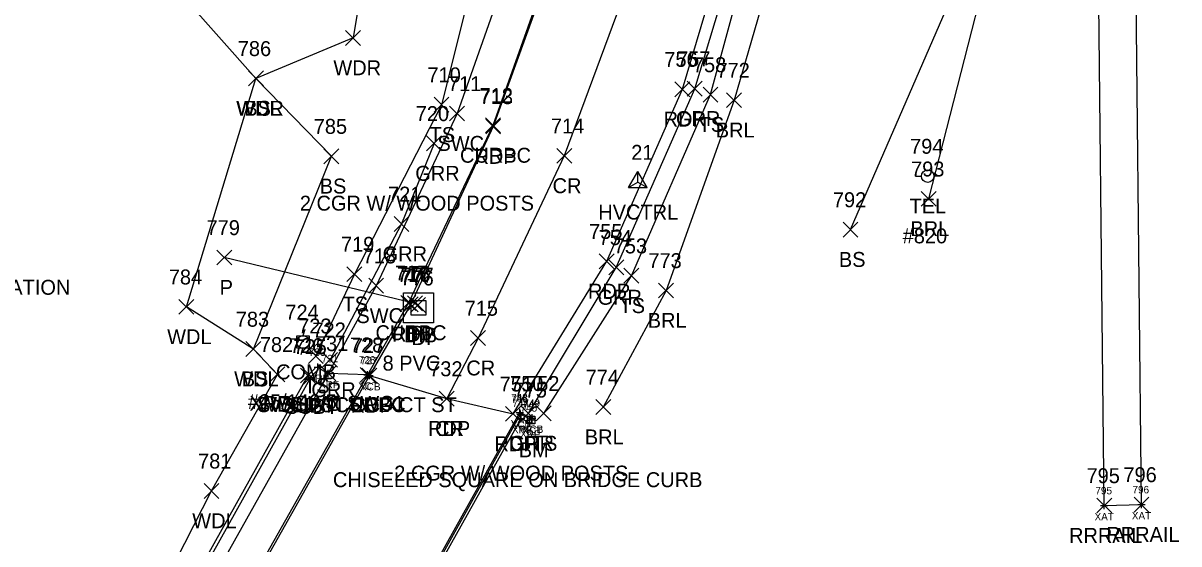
# Model space of a CAD drawing. Extents: x 1764889 to 1767296, y 695936 to 698960.
# Drawn here: x 1766265.6 to 1766420.4, y 696326.9 to 696396.7 of the extents above; entities that cross this region are included whole.
import ezdxf

# ---------------------------------------------------------------- set-up
doc = ezdxf.new("R2010")
doc.units = 0
for name, color, linetype in [('B_A', 7, 'Continuous'), ('B_I', 7, 'Continuous'), ('B_TIC', 7, 'Continuous'), ('BDC', 7, 'Continuous'), ('BR', 7, 'Continuous'), ('BSUBM', 7, 'Continuous'), ('C_A', 7, 'Continuous'), ('C_C', 7, 'Continuous'), ('C_I', 7, 'Continuous'), ('CPBM', 7, 'Continuous'), ('CPSM', 7, 'Continuous'), ('D_A', 7, 'Continuous'), ('D_C', 7, 'Continuous'), ('D_I', 7, 'Continuous'), ('D_TIC', 7, 'Continuous'), ('DCP', 7, 'Continuous'), ('DS', 7, 'Continuous'), ('L_A', 7, 'Continuous'), ('L_I', 7, 'Continuous'), ('L_TIC', 7, 'Continuous'), ('LABL', 7, 'Continuous'), ('LAWA', 7, 'Continuous'), ('LELB', 7, 'Continuous'), ('P_A', 7, 'Continuous'), ('P_I', 7, 'Continuous'), ('P_TIC', 7, 'Continuous'), ('PET', 7, 'Continuous'), ('PRC', 7, 'Continuous'), ('R_A', 7, 'Continuous'), ('R_C', 7, 'Continuous'), ('R_I', 7, 'Continuous'), ('R_TIC', 7, 'Continuous'), ('RC', 7, 'Continuous'), ('RGR', 7, 'Continuous'), ('RR', 7, 'Continuous'), ('RSW', 7, 'Continuous'), ('U_A', 7, 'Continuous'), ('U_C', 7, 'Continuous'), ('U_I', 7, 'Continuous'), ('U_TIC', 7, 'Continuous'), ('UP', 7, 'Continuous'), ('UT', 7, 'Continuous')]:
    doc.layers.add(name, color=color, linetype=linetype)

msp = doc.modelspace()

# ---------------------------------------------------------------- linework, layer by layer
at = {"layer": 'B_TIC'}
for p, q in [((1766305.11, 696350.62), (1766305.18, 696350.62)), ((1766306.5, 696349.77), (1766306.57, 696349.77)), ((1766311.76, 696349.59), (1766311.83, 696349.59)), ((1766312, 696349.5), (1766312.08, 696349.5)), ((1766332.16, 696344.53), (1766332.23, 696344.53)), ((1766332.25, 696344.32), (1766332.32, 696344.32)), ((1766332.33, 696343.76), (1766332.4, 696343.76)), ((1766333.42, 696343.16), (1766333.5, 696343.16)), ((1766333.75, 696343.56), (1766333.82, 696343.56)), ((1766333.81, 696343.8), (1766333.88, 696343.8)), ((1766410.41, 696332.08), (1766410.48, 696332.08)), ((1766415.4, 696332.21), (1766415.47, 696332.21))]:
    msp.add_line(p, q, dxfattribs=at)
for points in [[(1766304.61, 696350.62), (1766305.61, 696350.62)], [(1766305.11, 696350.12), (1766305.11, 696351.12)], [(1766305.99, 696349.77), (1766306.99, 696349.77)], [(1766306.49, 696349.27), (1766306.49, 696350.27)], [(1766311.25, 696349.59), (1766312.25, 696349.59)], [(1766311.5, 696349.5), (1766312.5, 696349.5)], [(1766311.75, 696349.09), (1766311.75, 696350.09)], [(1766312, 696349), (1766312, 696350)], [(1766331.65, 696344.53), (1766332.65, 696344.53)], [(1766331.74, 696344.32), (1766332.74, 696344.32)], [(1766332.15, 696344.03), (1766332.15, 696345.03)], [(1766332.24, 696343.82), (1766332.24, 696344.82)], [(1766332.32, 696343.26), (1766332.32, 696344.26)], [(1766333.8, 696343.3), (1766333.8, 696344.3)], [(1766331.82, 696343.76), (1766332.82, 696343.76)], [(1766332.92, 696343.16), (1766333.92, 696343.16)], [(1766333.24, 696343.56), (1766334.24, 696343.56)], [(1766333.3, 696343.8), (1766334.3, 696343.8)], [(1766333.42, 696342.66), (1766333.42, 696343.66)], [(1766333.74, 696343.06), (1766333.74, 696344.06)], [(1766409.91, 696332.08), (1766410.91, 696332.08)], [(1766410.41, 696331.58), (1766410.41, 696332.58)], [(1766414.9, 696332.21), (1766415.9, 696332.21)], [(1766415.4, 696331.71), (1766415.4, 696332.71)]]:
    msp.add_lwpolyline(points, dxfattribs=at)
at = {"layer": 'BDC'}
for points in [[(1766311.75, 696349.59), (1766247.58, 696235.94)], [(1766312, 696349.5), (1766247.9, 696235.86)], [(1766268.89, 696231.13), (1766332.15, 696344.53), (1766333.8, 696343.8)], [(1766269.14, 696230.99), (1766332.24, 696344.32), (1766333.74, 696343.56)]]:
    msp.add_lwpolyline(points, dxfattribs=at)
at = {"layer": 'BR'}
for points in [[(1766305.11, 696350.62), (1766306.49, 696349.77), (1766243.27, 696237.04), (1766242.22, 696237.68)], [(1766270.49, 696230.33), (1766269.37, 696231.11), (1766332.32, 696343.76), (1766333.42, 696343.16)]]:
    msp.add_lwpolyline(points, dxfattribs=at)
at = {"layer": 'BSUBM'}
msp.add_lwpolyline([(1766410.41, 696332.08), (1766415.4, 696332.21)], dxfattribs=at)
at = {"layer": 'CPBM'}
for p, q in [((1766333.17, 696343.04), (1766333.17, 696344.04)), ((1766333.17, 696344.04), (1766334.17, 696344.04)), ((1766334.17, 696343.04), (1766333.17, 696343.04)), ((1766333.67, 696343.54), (1766333.67, 696343.54)), ((1766333.67, 696343.54), (1766333.67, 696343.54)), ((1766334.17, 696344.04), (1766334.17, 696343.04))]:
    msp.add_line(p, q, dxfattribs=at)
at = {"layer": 'CPSM'}
for p, q in [((1766346.71, 696374.68), (1766347.96, 696376.84)), ((1766349.21, 696374.68), (1766347.96, 696376.84)), ((1766347.96, 696375.4), (1766347.96, 696376.84)), ((1766346.71, 696374.68), (1766347.96, 696375.4)), ((1766347.96, 696375.4), (1766347.96, 696375.4)), ((1766347.96, 696375.4), (1766349.21, 696374.68)), ((1766346.71, 696374.68), (1766349.21, 696374.68))]:
    msp.add_line(p, q, dxfattribs=at)
at = {"layer": 'D_TIC'}
for points in [[(1766291.56, 696364.31), (1766293.56, 696366.31)], [(1766293.56, 696364.31), (1766291.56, 696366.31)], [(1766317.1, 696358.16), (1766319.1, 696360.16)], [(1766319.1, 696358.16), (1766317.1, 696360.16)], [(1766317.51, 696357.93), (1766319.51, 696359.93)], [(1766319.51, 696357.93), (1766317.51, 696359.93)]]:
    msp.add_lwpolyline(points, dxfattribs=at)
at = {"layer": 'DCP'}
msp.add_lwpolyline([(1766318.1, 696359.16), (1766292.56, 696365.31)], dxfattribs=at)
at = {"layer": 'DS'}
for p, q in [((1766316.57, 696360.57), (1766320.57, 696360.57)), ((1766316.57, 696356.57), (1766316.57, 696360.57)), ((1766320.57, 696360.57), (1766320.57, 696356.57)), ((1766317.57, 696357.57), (1766317.57, 696359.57)), ((1766317.57, 696359.57), (1766319.57, 696359.57)), ((1766318.57, 696358.57), (1766318.57, 696358.57)), ((1766318.57, 696358.57), (1766318.57, 696358.57)), ((1766319.57, 696359.57), (1766319.57, 696357.57)), ((1766320.57, 696356.57), (1766316.57, 696356.57)), ((1766319.57, 696357.57), (1766317.57, 696357.57))]:
    msp.add_line(p, q, dxfattribs=at)
at = {"layer": 'L_TIC'}
for points in [[(1766308.8, 696393.73), (1766310.8, 696395.73)], [(1766310.8, 696393.73), (1766308.8, 696395.73)], [(1766295.79, 696388.3), (1766297.79, 696390.3)], [(1766297.79, 696388.3), (1766295.79, 696390.3)], [(1766295.79, 696388.3), (1766297.79, 696390.3)], [(1766297.79, 696388.3), (1766295.79, 696390.3)], [(1766295.79, 696388.3), (1766297.79, 696390.3)], [(1766297.79, 696388.3), (1766295.79, 696390.3)], [(1766356.68, 696386.14), (1766358.68, 696388.14)], [(1766358.68, 696386.14), (1766356.68, 696388.14)], [(1766320.65, 696384.78), (1766322.65, 696386.78)], [(1766322.65, 696384.78), (1766320.65, 696386.78)], [(1766359.84, 696385.39), (1766361.84, 696387.39)], [(1766361.84, 696385.39), (1766359.84, 696387.39)], [(1766305.9, 696377.88), (1766307.9, 696379.88)], [(1766307.9, 696377.88), (1766305.9, 696379.88)], [(1766385.9, 696372.17), (1766387.9, 696374.17)], [(1766387.9, 696372.17), (1766385.9, 696374.17)], [(1766375.43, 696368.05), (1766377.43, 696370.05)], [(1766377.43, 696368.05), (1766375.43, 696370.05)], [(1766308.99, 696362.08), (1766310.99, 696364.08)], [(1766310.99, 696362.08), (1766308.99, 696364.08)], [(1766346.08, 696361.86), (1766348.08, 696363.86)], [(1766348.08, 696361.86), (1766346.08, 696363.86)], [(1766350.73, 696359.89), (1766352.73, 696361.89)], [(1766352.73, 696359.89), (1766350.73, 696361.89)], [(1766286.49, 696357.7), (1766288.49, 696359.7)], [(1766288.49, 696357.7), (1766286.49, 696359.7)], [(1766295.46, 696352.04), (1766297.46, 696354.04)], [(1766297.46, 696352.04), (1766295.46, 696354.04)], [(1766295.46, 696352.04), (1766297.46, 696354.04)], [(1766297.46, 696352.04), (1766295.46, 696354.04)], [(1766303.82, 696351.13), (1766305.82, 696353.13)], [(1766305.82, 696351.13), (1766303.82, 696353.13)], [(1766298.68, 696348.64), (1766300.68, 696350.64)], [(1766300.68, 696348.64), (1766298.68, 696350.64)], [(1766342.31, 696344.27), (1766344.31, 696346.27)], [(1766344.31, 696344.27), (1766342.31, 696346.27)], [(1766334.34, 696343.42), (1766336.34, 696345.42)], [(1766336.34, 696343.42), (1766334.34, 696345.42)], [(1766289.85, 696333.04), (1766291.85, 696335.04)], [(1766291.85, 696333.04), (1766289.85, 696335.04)]]:
    msp.add_lwpolyline(points, dxfattribs=at)
at = {"layer": 'LABL'}
for points in [[(1766374.47, 696463.57), (1766373.43, 696438.78), (1766368.2, 696411.81), (1766360.84, 696386.39), (1766351.73, 696360.89), (1766343.31, 696345.27)], [(1766386.9, 696373.17), (1766399.38, 696421.91), (1766388.69, 696460.88)]]:
    msp.add_lwpolyline(points, dxfattribs=at)
at = {"layer": 'LAWA'}
for points in [[(1766330.95, 696497.09), (1766332.88, 696464.35), (1766327.13, 696431.55), (1766322.82, 696417.68), (1766312.1, 696408.54), (1766309.8, 696394.73), (1766296.79, 696389.3)], [(1766283.72, 696320.03), (1766290.85, 696334.04), (1766299.68, 696349.64), (1766296.46, 696353.04), (1766287.49, 696358.7), (1766296.79, 696389.3)]]:
    msp.add_lwpolyline(points, dxfattribs=at)
at = {"layer": 'LELB'}
for points in [[(1766376.43, 696369.05), (1766399.38, 696421.91), (1766400.57, 696461.93), (1766402.32, 696486.13), (1766401.07, 696549.52), (1766401.07, 696591.37), (1766401.28, 696644.9)], [(1766328.84, 696531.83), (1766335.43, 696500.85), (1766336.09, 696495.53), (1766337.65, 696452.52), (1766334.4, 696430.54), (1766327.65, 696409.72), (1766321.65, 696385.78), (1766309.99, 696363.08), (1766304.82, 696352.13)], [(1766296.46, 696353.04), (1766306.9, 696378.88), (1766296.79, 696389.3), (1766282.62, 696405.27), (1766276.49, 696419.77), (1766284.48, 696446.68), (1766298.94, 696470.27), (1766309.93, 696473.86), (1766308.83, 696479.36), (1766301.06, 696490.57), (1766293.47, 696488.5)], [(1766335.34, 696344.42), (1766347.08, 696362.86), (1766357.68, 696387.14), (1766365.68, 696416.43), (1766371.22, 696451.45), (1766371.63, 696487)]]:
    msp.add_lwpolyline(points, dxfattribs=at)
at = {"layer": 'P_TIC'}
for points in [[(1766352.91, 696386.85), (1766354.91, 696388.85)], [(1766354.91, 696386.85), (1766352.91, 696388.85)], [(1766327.57, 696381.86), (1766329.57, 696383.86)], [(1766329.57, 696381.86), (1766327.57, 696383.86)], [(1766337.09, 696377.93), (1766339.09, 696379.93)], [(1766339.09, 696377.93), (1766337.09, 696379.93)], [(1766342.78, 696363.8), (1766344.78, 696365.8)], [(1766344.78, 696363.8), (1766342.78, 696365.8)], [(1766316.54, 696358.04), (1766318.54, 696360.04)], [(1766318.54, 696358.04), (1766316.54, 696360.04)], [(1766325.54, 696353.51), (1766327.54, 696355.51)], [(1766327.54, 696353.51), (1766325.54, 696355.51)], [(1766311, 696348.5), (1766313, 696350.5)], [(1766313, 696348.5), (1766311, 696350.5)], [(1766321.36, 696345.4), (1766323.36, 696347.4)], [(1766323.36, 696345.4), (1766321.36, 696347.4)], [(1766321.36, 696345.4), (1766323.36, 696347.4)], [(1766323.36, 696345.4), (1766321.36, 696347.4)], [(1766330.24, 696343.36), (1766332.24, 696345.36)], [(1766332.24, 696343.36), (1766330.24, 696345.36)]]:
    msp.add_lwpolyline(points, dxfattribs=at)
at = {"layer": 'PET'}
msp.add_lwpolyline([(1766331.65, 696550.27), (1766337.19, 696529.87), (1766342.79, 696505.62), (1766343.93, 696497.35), (1766345.9, 696477.35), (1766345.61, 696451.13), (1766342.46, 696428.54), (1766337.12, 696406.59), (1766328.57, 696382.86), (1766317.54, 696359.04), (1766312, 696349.5), (1766322.36, 696346.4), (1766331.24, 696344.36), (1766343.78, 696364.8), (1766353.91, 696387.85), (1766362.68, 696417.29), (1766367.96, 696451.25), (1766367.19, 696487.5)], dxfattribs=at)
at = {"layer": 'PRC'}
msp.add_lwpolyline([(1766338.9, 696564.49), (1766342.21, 696553.11), (1766347.54, 696534.73), (1766353.36, 696507.93), (1766356.46, 696477.18), (1766356.12, 696449.17), (1766352.9, 696426.11), (1766347.27, 696403.75), (1766338.09, 696378.93), (1766326.54, 696354.51), (1766322.36, 696346.4)], dxfattribs=at)
at = {"layer": 'R_TIC'}
for points in [[(1766354.56, 696386.92), (1766356.56, 696388.92)], [(1766356.56, 696386.92), (1766354.56, 696388.92)], [(1766322.74, 696383.6), (1766324.74, 696385.6)], [(1766324.74, 696383.6), (1766322.74, 696385.6)], [(1766327.54, 696382.01), (1766329.54, 696384.01)], [(1766329.54, 696382.01), (1766327.54, 696384.01)], [(1766319.65, 696379.59), (1766321.65, 696381.59)], [(1766321.65, 696379.59), (1766319.65, 696381.59)], [(1766315.29, 696368.8), (1766317.29, 696370.8)], [(1766317.29, 696368.8), (1766315.29, 696370.8)], [(1766344.06, 696362.98), (1766346.06, 696364.98)], [(1766346.06, 696362.98), (1766344.06, 696364.98)], [(1766311.9, 696360.52), (1766313.9, 696362.52)], [(1766313.9, 696360.52), (1766311.9, 696362.52)], [(1766316.22, 696358.23), (1766318.22, 696360.23)], [(1766318.22, 696358.23), (1766316.22, 696360.23)], [(1766305.73, 696350.6), (1766307.73, 696352.6)], [(1766307.73, 696350.6), (1766305.73, 696352.6)], [(1766305.49, 696348.77), (1766307.49, 696350.77)], [(1766307.49, 696348.77), (1766305.49, 696350.77)], [(1766305.49, 696348.77), (1766307.49, 696350.77)], [(1766307.49, 696348.77), (1766305.49, 696350.77)], [(1766310.75, 696348.59), (1766312.75, 696350.59)], [(1766312.75, 696348.59), (1766310.75, 696350.59)], [(1766310.75, 696348.59), (1766312.75, 696350.59)], [(1766312.75, 696348.59), (1766310.75, 696350.59)], [(1766332.29, 696343.42), (1766334.29, 696345.42)], [(1766334.29, 696343.42), (1766332.29, 696345.42)], [(1766409.41, 696331.08), (1766411.41, 696333.08)], [(1766411.41, 696331.08), (1766409.41, 696333.08)], [(1766414.4, 696331.21), (1766416.4, 696333.21)], [(1766416.4, 696331.21), (1766414.4, 696333.21)]]:
    msp.add_lwpolyline(points, dxfattribs=at)
at = {"layer": 'RC'}
msp.add_lwpolyline([(1766331.2, 696549.96), (1766337.06, 696529.85), (1766342.58, 696505.51), (1766343.74, 696497.37), (1766345.77, 696477.42), (1766345.44, 696451.09), (1766342.29, 696428.54), (1766336.95, 696406.74), (1766328.54, 696383.01), (1766317.22, 696359.23), (1766311.75, 696349.59)], dxfattribs=at)
at = {"layer": 'RGR'}
for points in [[(1766333.29, 696344.42), (1766345.06, 696363.98), (1766355.56, 696387.92), (1766364.33, 696416.92), (1766369.13, 696451.48), (1766368.76, 696487.08)], [(1766320.65, 696380.59), (1766316.29, 696369.8), (1766306.73, 696351.6)]]:
    msp.add_lwpolyline(points, dxfattribs=at)
at = {"layer": 'RR'}
for points in [[(1766415.4, 696332.21), (1766414.47, 696421.49), (1766413.91, 696486.12), (1766413.47, 696550.63), (1766413.06, 696590.68), (1766412.95, 696642.7), (1766413.23, 696713.18), (1766413.82, 696750.29), (1766414.9, 696799.38)], [(1766410.41, 696332.08), (1766409.46, 696420.45), (1766408.85, 696485.76), (1766408.53, 696550.3), (1766408.18, 696590.82), (1766408.03, 696642.92), (1766408.33, 696712.56), (1766409.02, 696750.78), (1766409.91, 696798.98)]]:
    msp.add_lwpolyline(points, dxfattribs=at)
at = {"layer": 'RSW'}
for points in [[(1766331.2, 696549.96), (1766327.58, 696544.87), (1766332.36, 696528.32), (1766337.43, 696504.73), (1766338.8, 696496.93), (1766340.76, 696477.25), (1766340.46, 696451.69), (1766337.58, 696429.77), (1766332.16, 696408.41), (1766323.74, 696384.6), (1766312.9, 696361.52), (1766306.49, 696349.77)], [(1766311.75, 696349.59), (1766306.49, 696349.77)]]:
    msp.add_lwpolyline(points, dxfattribs=at)
at = {"layer": 'U_TIC'}
for points in [[(1766302.75, 696348.5), (1766304.75, 696350.5)], [(1766304.75, 696348.5), (1766302.75, 696350.5)], [(1766303.18, 696348.36), (1766305.18, 696350.36)], [(1766305.18, 696348.36), (1766303.18, 696350.36)]]:
    msp.add_lwpolyline(points, dxfattribs=at)
at = {"layer": 'UP'}
for p, q in [((1766385.11, 696376.2), (1766385.94, 696376.2)), ((1766386.77, 696376.21), (1766386.77, 696376.21)), ((1766388.44, 696376.21), (1766387.6, 696376.21)), ((1766387.6, 696376.21), (1766387.6, 696376.21)), ((1766388.44, 696376.21), (1766388.44, 696376.21)), ((1766303.35, 696355.66), (1766303.1, 696354.83)), ((1766302.27, 696353.16), (1766302.27, 696354.83)), ((1766302.27, 696354.83), (1766303.93, 696354.83)), ((1766303.1, 696353.99), (1766303.1, 696353.99)), ((1766303.93, 696354.83), (1766303.93, 696353.16)), ((1766303.93, 696353.16), (1766302.27, 696353.16)), ((1766302.85, 696352.33), (1766303.1, 696353.16))]:
    msp.add_line(p, q, dxfattribs=at)
for centre in [(1766386.77, 696376.21), (1766303.1, 696353.99)]:
    msp.add_circle(centre, 0.833, dxfattribs=at)
at = {"layer": 'UT'}
for points in [[(1766303.75, 696349.5), (1766242.47, 696239.78)], [(1766304.18, 696349.36), (1766242.77, 696239.3)]]:
    msp.add_lwpolyline(points, dxfattribs=at)

# ---------------------------------------------------------------- texts
at = {"layer": 'B_A'}
for s, p in [('XRF', (1766303.87, 696348.62)), ('XRF', (1766305.25, 696347.77)), ('XCT', (1766310.48, 696347.59)), ('XCB', (1766310.74, 696347.5)), ('XCB', (1766330.89, 696342.53)), ('XCT', (1766330.96, 696342.32)), ('XRF', (1766331.08, 696341.76)), ('XCT', (1766332.46, 696341.56)), ('XCB', (1766332.54, 696341.8)), ('XRF', (1766332.18, 696341.16)), ('XAT', (1766409.11, 696330.08)), ('XAT', (1766414.1, 696330.21))]:
    msp.add_text(s, height=1, dxfattribs=at).set_placement(p)
at = {"layer": 'B_I'}
for s, p in [('730', (1766303.88, 696352.12)), ('731', (1766305.6, 696351.27)), ('728', (1766310.57, 696351.09)), ('727', (1766310.82, 696351)), ('748', (1766330.97, 696346.03)), ('746', (1766331.03, 696345.82)), ('744', (1766331.14, 696345.26)), ('745', (1766332.24, 696344.66)), ('747', (1766332.56, 696345.06)), ('749', (1766332.62, 696345.3)), ('795', (1766409.22, 696333.58)), ('796', (1766414.19, 696333.71))]:
    msp.add_text(s, height=1, dxfattribs=at).set_placement(p)
at = {"layer": 'C_A'}
for s, p in [('HVCTRL', (1766342.65, 696370.4)), ('BM', (1766331.99, 696338.54))]:
    msp.add_text(s, height=2, dxfattribs=at).set_placement(p)
at = {"layer": 'C_C'}
msp.add_text('CHISELED SQUARE ON BRIDGE CURB', height=2, dxfattribs=at).set_placement((1766307.11, 696334.54))
at = {"layer": 'C_I'}
for s, p in [('21', (1766347.06, 696378.4)), ('775', (1766331.31, 696346.54))]:
    msp.add_text(s, height=2, dxfattribs=at).set_placement(p)
at = {"layer": 'D_A'}
for s, p in [('P', (1766291.94, 696360.31)), ('DIB', (1766316.61, 696353.93)), ('P', (1766317.48, 696354.16)), ('DI', (1766317.63, 696353.57))]:
    msp.add_text(s, height=2, dxfattribs=at).set_placement(p)
at = {"layer": 'D_C'}
msp.add_text('8 PVC', height=2, dxfattribs=at).set_placement((1766313.76, 696350.16))
at = {"layer": 'D_I'}
for s, p in [('779', (1766290.19, 696368.31)), ('778', (1766315.74, 696362.16)), ('777', (1766316.15, 696361.93)), ('776', (1766316.15, 696361.57))]:
    msp.add_text(s, height=2, dxfattribs=at).set_placement(p)
at = {"layer": 'L_A'}
for s, p in [('WDR', (1766307.17, 696389.73)), ('WDR', (1766294.15, 696384.3)), ('WDL', (1766294.2, 696384.3)), ('BS', (1766295.23, 696384.3)), ('TS', (1766320.06, 696380.78)), ('TS', (1766356.09, 696382.14)), ('BRL', (1766358.38, 696381.39)), ('BS', (1766305.34, 696373.88)), ('BRL', (1766384.45, 696368.17)), ('BS', (1766374.87, 696364.05)), ('FOUNDATION', (1766254.26, 696360.32)), ('FOUNDATION', (1766254.26, 696360.32)), ('TS', (1766308.4, 696358.08)), ('TS', (1766345.49, 696357.86)), ('BRL', (1766349.27, 696355.89)), ('WDL', (1766284.91, 696353.7)), ('WDL', (1766293.88, 696348.04)), ('BS', (1766294.9, 696348.04)), ('TS', (1766303.23, 696347.13)), ('WDL', (1766297.1, 696344.64)), ('TS', (1766333.75, 696339.42)), ('BRL', (1766340.85, 696340.27)), ('WDL', (1766288.27, 696329.04))]:
    msp.add_text(s, height=2, dxfattribs=at).set_placement(p)
at = {"layer": 'L_I'}
for s, p in [('786', (1766294.37, 696392.3)), ('786', (1766294.37, 696392.3)), ('786', (1766294.37, 696392.3)), ('758', (1766355.32, 696390.14)), ('710', (1766319.77, 696388.78)), ('772', (1766358.48, 696389.39)), ('785', (1766304.54, 696381.88)), ('793', (1766384.54, 696376.17)), ('792', (1766374.07, 696372.05)), ('719', (1766308.19, 696366.08)), ('753', (1766344.72, 696365.86)), ('773', (1766349.36, 696363.89)), ('784', (1766285.13, 696361.7)), ('783', (1766294.1, 696356.04)), ('783', (1766294.1, 696356.04)), ('723', (1766302.46, 696355.13)), ('782', (1766297.32, 696352.64)), ('752', (1766332.98, 696347.42)), ('774', (1766340.95, 696348.27)), ('781', (1766289.05, 696337.04))]:
    msp.add_text(s, height=2, dxfattribs=at).set_placement(p)
at = {"layer": 'P_A'}
for s, p in [('RDP', (1766351.4, 696382.85)), ('RDP', (1766326.06, 696377.86)), ('CR', (1766336.53, 696373.93)), ('RDP', (1766341.27, 696359.8)), ('RDP', (1766315.03, 696354.04)), ('CR', (1766324.98, 696349.51)), ('RDP', (1766309.49, 696344.5)), ('RDP', (1766319.85, 696341.4)), ('CR', (1766320.79, 696341.4)), ('RDP', (1766328.73, 696339.36))]:
    msp.add_text(s, height=2, dxfattribs=at).set_placement(p)
at = {"layer": 'P_I'}
for s, p in [('756', (1766351.49, 696390.85)), ('713', (1766326.77, 696385.86)), ('714', (1766336.3, 696381.93)), ('755', (1766341.42, 696367.8)), ('716', (1766315.69, 696362.04)), ('715', (1766324.75, 696357.51)), ('727', (1766309.64, 696352.5)), ('732', (1766320, 696349.4)), ('732', (1766320, 696349.4)), ('751', (1766329.44, 696347.36))]:
    msp.add_text(s, height=2, dxfattribs=at).set_placement(p)
at = {"layer": 'R_A'}
for s, p in [('GRR', (1766353.05, 696382.92)), ('SWC', (1766321.11, 696379.6)), ('CURBC', (1766324.13, 696378.01)), ('GRR', (1766318.14, 696375.59)), ('GRR', (1766313.77, 696364.8)), ('GRR', (1766342.55, 696358.98)), ('SWC', (1766310.26, 696356.52)), ('CURBC', (1766312.81, 696354.23)), ('GRR', (1766304.22, 696346.6)), ('XRF SWC SWC1', (1766295.93, 696344.77)), ('XRF SWC SWC1', (1766295.93, 696344.77)), ('SWC1 ST CC XCT ST', (1766296.94, 696344.59)), ('CURBC', (1766307.34, 696344.59)), ('GRR', (1766330.77, 696339.42)), ('RRRAIL', (1766405.7, 696327.08)), ('RRRAIL', (1766410.69, 696327.21))]:
    msp.add_text(s, height=2, dxfattribs=at).set_placement(p)
at = {"layer": 'R_C'}
for p in [(1766302.68, 696371.59), (1766315.32, 696335.42)]:
    msp.add_text('2 CGR W/ WOOD POSTS', height=2, dxfattribs=at).set_placement(p)
at = {"layer": 'R_I'}
for s, p in [('757', (1766353.2, 696390.92)), ('711', (1766322.52, 696387.6)), ('712', (1766326.75, 696386.01)), ('720', (1766318.2, 696383.59)), ('721', (1766314.49, 696372.8)), ('754', (1766342.7, 696366.98)), ('718', (1766311.11, 696364.52)), ('717', (1766315.43, 696362.23)), ('722', (1766304.37, 696354.6)), ('731', (1766304.7, 696352.77)), ('731', (1766304.7, 696352.77)), ('728', (1766309.39, 696352.59)), ('728', (1766309.39, 696352.59)), ('750', (1766330.84, 696347.42)), ('795', (1766408.04, 696335.08)), ('796', (1766412.98, 696335.21))]:
    msp.add_text(s, height=2, dxfattribs=at).set_placement(p)
at = {"layer": 'U_A'}
for s, p in [('TEL', (1766384.33, 696371.21)), ('COMB', (1766299.49, 696348.99)), ('SUBT', (1766300.25, 696344.5)), ('SUBT', (1766300.68, 696344.36))]:
    msp.add_text(s, height=2, dxfattribs=at).set_placement(p)
at = {"layer": 'U_C'}
for s, p in [('#820', (1766383.42, 696367.21)), ('#25/146/5', (1766295.71, 696344.99))]:
    msp.add_text(s, height=2, dxfattribs=at).set_placement(p)
at = {"layer": 'U_I'}
for s, p in [('794', (1766384.41, 696379.21)), ('724', (1766300.74, 696356.99)), ('726', (1766301.34, 696352.5)), ('725', (1766301.82, 696352.36))]:
    msp.add_text(s, height=2, dxfattribs=at).set_placement(p)

doc.saveas('drawing.dxf')
